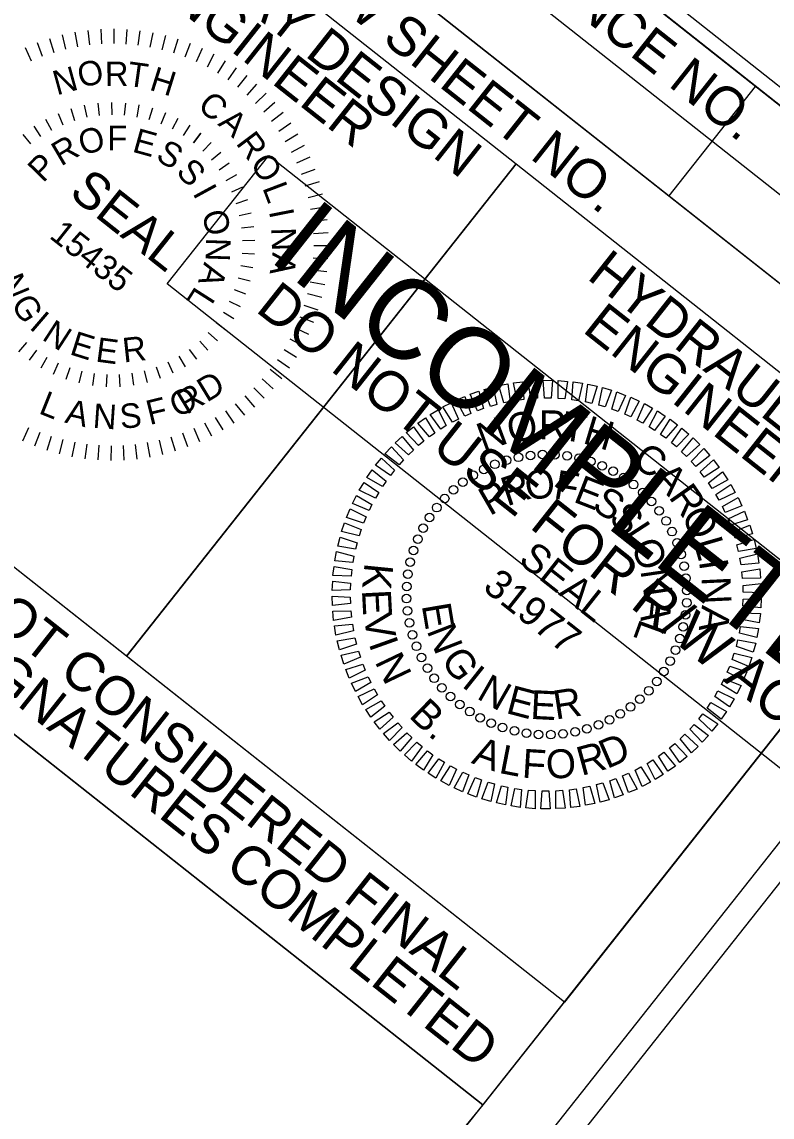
# Model space of a CAD drawing. Extents: x 557005 to 559009, y 505746 to 507841.
# Drawn here: x 558789.4 to 558923.8, y 506648.8 to 506845.2 of the extents above; entities that cross this region are included whole.
import ezdxf

# ---------------------------------------------------------------- set-up
doc = ezdxf.new("R2010")
doc.units = 0
for name, color, linetype in [('Old_Level_21', 7, 'Continuous'), ('Scratch_Level_5', 7, 'Continuous'), ('Sheet Border Standard 30in CELL', 7, 'Continuous'), ('Sheet Plot Border Inside CELL', 7, 'Continuous'), ('Sheet Plot Border Outside CELL', 7, 'Continuous'), ('Sheet Sticker Exception Certification CELL', 7, 'Continuous'), ('Sheet Sticker Incomplete CELL', 7, 'Continuous')]:
    doc.layers.add(name, color=color, linetype=linetype)

msp = doc.modelspace()

# ---------------------------------------------------------------- linework, layer by layer
at = {"layer": 'Old_Level_21'}
for p, q in [((558794.37, 506842.22), (558795.14, 506839.7)), ((558796.62, 506842.83), (558797.24, 506840.27)), ((558798.91, 506843.31), (558799.37, 506840.71)), ((558801.22, 506843.64), (558801.53, 506841.03)), ((558803.55, 506843.84), (558803.7, 506841.21)), ((558805.89, 506843.9), (558805.87, 506841.27)), ((558808.22, 506843.82), (558808.05, 506841.19)), ((558810.55, 506843.59), (558810.22, 506840.98)), ((558812.86, 506843.23), (558812.37, 506840.64)), ((558815.14, 506842.72), (558814.49, 506840.17)), ((558789.99, 506840.59), (558791.06, 506838.17)), ((558792.16, 506841.47), (558793.07, 506839)), ((558817.39, 506842.08), (558816.59, 506839.57)), ((558819.59, 506841.31), (558818.64, 506838.85)), ((558821.75, 506840.4), (558820.65, 506838)), ((558823.84, 506839.37), (558822.6, 506837.04)), ((558825.87, 506838.2), (558824.49, 506835.96)), ((558827.82, 506836.92), (558826.31, 506834.77)), ((558829.7, 506835.53), (558828.06, 506833.46)), ((558831.48, 506834.02), (558829.72, 506832.06)), ((558833.17, 506832.41), (558831.3, 506830.56)), ((558803.04, 506830.58), (558803.27, 506828.39)), ((558805.5, 506830.71), (558805.51, 506828.51)), ((558807.96, 506830.61), (558807.76, 506828.42)), ((558834.77, 506830.7), (558832.78, 506828.96)), ((558795.9, 506828.77), (558796.74, 506826.74)), ((558798.22, 506829.61), (558798.86, 506827.5)), ((558800.61, 506830.21), (558801.04, 506828.06)), ((558810.4, 506830.27), (558809.99, 506828.11)), ((558812.8, 506829.7), (558812.18, 506827.59)), ((558815.13, 506828.89), (558814.31, 506826.85)), ((558836.25, 506828.9), (558834.17, 506827.28)), ((558791.56, 506826.46), (558792.78, 506824.63)), ((558793.67, 506827.72), (558794.71, 506825.78)), ((558817.37, 506827.87), (558816.36, 506825.92)), ((558819.5, 506826.63), (558818.31, 506824.79)), ((558837.63, 506827.01), (558835.45, 506825.52)), ((558789.57, 506825), (558790.96, 506823.29)), ((558821.5, 506825.19), (558820.14, 506823.47)), ((558820.14, 506823.47), (558821.5, 506825.19)), ((558838.88, 506825.04), (558836.62, 506823.69)), ((558823.36, 506823.57), (558821.83, 506821.99)), ((558840.01, 506822.99), (558837.68, 506821.78)), ((558825.04, 506821.78), (558823.37, 506820.35)), ((558841.03, 506820.89), (558838.62, 506819.82)), ((558826.55, 506819.83), (558824.75, 506818.57)), ((558841.91, 506818.72), (558839.44, 506817.8)), ((558827.87, 506817.75), (558825.95, 506816.67)), ((558828.97, 506815.55), (558826.96, 506814.65)), ((558842.66, 506816.51), (558840.14, 506815.74)), ((558829.86, 506813.25), (558827.77, 506812.55)), ((558843.27, 506814.26), (558840.71, 506813.64)), ((558830.52, 506810.87), (558828.38, 506810.39)), ((558843.75, 506811.97), (558841.15, 506811.51)), ((558844.09, 506809.66), (558841.47, 506809.35)), ((558830.95, 506808.45), (558828.77, 506808.17)), ((558844.29, 506807.33), (558841.65, 506807.18)), ((558831.14, 506805.99), (558828.95, 506805.93)), ((558844.34, 506804.99), (558841.71, 506805.01)), ((558831.1, 506803.53), (558828.91, 506803.67)), ((558844.26, 506802.66), (558841.63, 506802.83)), ((558830.82, 506801.09), (558828.65, 506801.44)), ((558830.3, 506798.67), (558828.18, 506799.24)), ((558844.04, 506800.33), (558841.42, 506800.66)), ((558829.55, 506796.33), (558827.49, 506797.1)), ((558843.67, 506798.02), (558841.08, 506798.51)), ((558828.59, 506794.06), (558826.61, 506795.02)), ((558843.16, 506795.74), (558840.61, 506796.39)), ((558827.4, 506791.9), (558825.53, 506793.05)), ((558842.53, 506793.49), (558840.01, 506794.29)), ((558826.02, 506789.86), (558824.26, 506791.19)), ((558841.75, 506791.29), (558839.29, 506792.24)), ((558824.44, 506787.97), (558822.82, 506789.46)), ((558840.84, 506789.13), (558838.45, 506790.23)), ((558788.87, 506786.03), (558790.32, 506787.69)), ((558821.28, 506787.93), (558822.75, 506786.3)), ((558839.81, 506787.04), (558837.48, 506788.28)), ((558790.8, 506784.5), (558792.09, 506786.28)), ((558818.72, 506783.32), (558817.6, 506785.21)), ((558820.77, 506784.68), (558819.47, 506786.45)), ((558838.65, 506785.01), (558836.4, 506786.39)), ((558792.87, 506783.16), (558793.97, 506785.06)), ((558795.06, 506782.03), (558795.97, 506784.03)), ((558797.35, 506781.12), (558798.06, 506783.2)), ((558814.27, 506781.22), (558813.53, 506783.29)), ((558816.55, 506782.17), (558815.61, 506784.15)), ((558837.37, 506783.06), (558835.21, 506784.57)), ((558799.71, 506780.43), (558800.23, 506782.57)), ((558802.14, 506779.97), (558802.44, 506782.15)), ((558804.59, 506779.75), (558804.68, 506781.94)), ((558807.05, 506779.76), (558806.93, 506781.96)), ((558809.5, 506780.02), (558809.17, 506782.18)), ((558811.92, 506780.5), (558811.37, 506782.63)), ((558835.97, 506781.18), (558833.9, 506782.82)), ((558832.85, 506777.71), (558831, 506779.58)), ((558834.46, 506779.4), (558832.5, 506781.16)), ((558831.14, 506776.11), (558829.41, 506778.1)), ((558827.45, 506773.25), (558825.96, 506775.43)), ((558829.34, 506774.63), (558827.72, 506776.71)), ((558825.48, 506772), (558824.13, 506774.26)), ((558789.58, 506770.04), (558790.68, 506772.43)), ((558791.73, 506769.13), (558792.68, 506771.59)), ((558819.16, 506768.97), (558818.25, 506771.44)), ((558821.33, 506769.85), (558820.26, 506772.26)), ((558823.44, 506770.87), (558822.22, 506773.2)), ((558793.93, 506768.35), (558794.73, 506770.87)), ((558796.18, 506767.72), (558796.83, 506770.27)), ((558798.46, 506767.21), (558798.96, 506769.8)), ((558800.77, 506766.84), (558801.1, 506769.46)), ((558812.41, 506767.13), (558811.95, 506769.73)), ((558814.7, 506767.61), (558814.08, 506770.17)), ((558816.95, 506768.22), (558816.18, 506770.74)), ((558803.1, 506766.62), (558803.27, 506769.25)), ((558805.43, 506766.54), (558805.45, 506769.17)), ((558807.77, 506766.59), (558807.63, 506769.23)), ((558810.1, 506766.79), (558809.8, 506769.41))]:
    msp.add_line(p, q, dxfattribs=at)
for points in [[(558873.37, 506776.23), (558872.26, 506779.27), (558873.88, 506779.69), (558874.5, 506776.56)], [(558875.75, 506776.85), (558874.85, 506779.96), (558876.5, 506780.27), (558876.9, 506777.1)], [(558878.16, 506777.31), (558877.49, 506780.47), (558879.15, 506780.66), (558879.33, 506777.47)], [(558880.6, 506777.59), (558880.15, 506780.79), (558881.82, 506780.87), (558881.78, 506777.68)], [(558883.06, 506777.71), (558882.83, 506780.93), (558884.51, 506780.89), (558884.24, 506777.71)], [(558885.52, 506777.65), (558885.52, 506780.88), (558887.18, 506780.72), (558886.7, 506777.57)], [(558887.96, 506777.42), (558888.19, 506780.64), (558889.84, 506780.37), (558889.14, 506777.25)], [(558890.39, 506777.02), (558890.84, 506780.22), (558892.47, 506779.83), (558891.55, 506776.77)], [(558892.78, 506776.45), (558893.45, 506779.61), (558895.05, 506779.11), (558893.92, 506776.12)], [(558868.77, 506774.5), (558867.25, 506777.36), (558868.8, 506778), (558869.85, 506774.98)], [(558871.04, 506775.45), (558869.72, 506778.4), (558871.31, 506778.94), (558872.15, 506775.85)], [(558895.13, 506775.71), (558896.02, 506778.82), (558897.58, 506778.21), (558896.24, 506775.31)], [(558897.42, 506774.82), (558898.52, 506777.86), (558900.03, 506777.14), (558898.5, 506774.34)], [(558864.46, 506772.15), (558862.55, 506774.76), (558864, 506775.62), (558865.46, 506772.78)], [(558866.57, 506773.4), (558864.86, 506776.14), (558866.35, 506776.89), (558867.62, 506773.96)], [(558899.64, 506773.77), (558900.95, 506776.72), (558902.41, 506775.9), (558900.68, 506773.21)], [(558901.78, 506772.56), (558903.3, 506775.42), (558904.7, 506774.5), (558902.78, 506771.93)], [(558862.43, 506770.75), (558860.35, 506773.23), (558861.73, 506774.18), (558863.39, 506771.45)], [(558903.83, 506771.21), (558905.55, 506773.95), (558906.88, 506772.94), (558904.79, 506770.51)], [(558860.51, 506769.22), (558858.27, 506771.54), (558859.57, 506772.59), (558861.42, 506769.98)], [(558905.79, 506769.72), (558907.69, 506772.33), (558908.94, 506771.23), (558906.69, 506768.96)], [(558858.71, 506767.55), (558856.3, 506769.71), (558857.53, 506770.85), (558859.56, 506768.37)], [(558907.63, 506768.09), (558909.71, 506770.57), (558910.89, 506769.38), (558908.48, 506767.27)], [(558857.02, 506765.76), (558854.47, 506767.75), (558855.62, 506768.97), (558857.81, 506766.64)], [(558909.36, 506766.34), (558911.6, 506768.67), (558912.69, 506767.4), (558910.15, 506765.46)], [(558855.46, 506763.86), (558852.78, 506765.67), (558853.84, 506766.96), (558856.19, 506764.8)], [(558910.96, 506764.48), (558913.36, 506766.64), (558914.36, 506765.3), (558911.69, 506763.55)], [(558854.04, 506761.86), (558851.23, 506763.47), (558852.2, 506764.84), (558854.7, 506762.84)], [(558912.43, 506762.51), (558914.97, 506764.5), (558915.88, 506763.09), (558913.09, 506761.52)], [(558852.76, 506759.76), (558849.85, 506761.18), (558850.72, 506762.61), (558853.35, 506760.78)], [(558913.75, 506760.43), (558916.43, 506762.24), (558917.24, 506760.77), (558914.34, 506759.41)], [(558851.63, 506757.58), (558848.63, 506758.79), (558849.4, 506760.27), (558852.14, 506758.64)], [(558914.93, 506758.28), (558917.73, 506759.9), (558918.43, 506758.37), (558915.45, 506757.21)], [(558850.65, 506755.32), (558847.58, 506756.32), (558848.24, 506757.85), (558851.09, 506756.42)], [(558915.95, 506756.04), (558918.86, 506757.46), (558919.45, 506755.89), (558916.4, 506754.95)], [(558849.84, 506753), (558846.7, 506753.78), (558847.25, 506755.36), (558850.2, 506754.13)], [(558916.82, 506753.74), (558919.82, 506754.96), (558920.3, 506753.35), (558917.19, 506752.62)], [(558849.18, 506750.63), (558846, 506751.19), (558846.44, 506752.81), (558849.47, 506751.78)], [(558917.52, 506751.39), (558920.6, 506752.39), (558920.97, 506750.75), (558917.81, 506750.24)], [(558848.7, 506748.22), (558845.48, 506748.56), (558845.81, 506750.2), (558848.91, 506749.39)], [(558918.06, 506748.99), (558921.2, 506749.77), (558921.45, 506748.12), (558918.27, 506747.82)], [(558848.39, 506745.78), (558845.15, 506745.89), (558845.37, 506747.55), (558848.51, 506746.96)], [(558918.43, 506746.56), (558921.62, 506747.12), (558921.75, 506745.45), (558918.56, 506745.38)], [(558848.24, 506743.33), (558845.01, 506743.21), (558845.11, 506744.89), (558848.28, 506744.51)], [(558918.63, 506744.11), (558921.85, 506744.45), (558921.86, 506742.77), (558918.67, 506742.93)], [(558848.27, 506740.87), (558845.05, 506740.53), (558845.03, 506742.21), (558848.23, 506742.05)], [(558918.66, 506741.65), (558921.89, 506741.76), (558921.79, 506740.09), (558918.62, 506740.47)], [(558848.47, 506738.42), (558845.28, 506737.86), (558845.15, 506739.53), (558848.34, 506739.6)], [(558918.51, 506739.2), (558921.74, 506739.08), (558921.53, 506737.42), (558918.39, 506738.02)], [(558848.84, 506735.99), (558845.7, 506735.21), (558845.45, 506736.86), (558848.63, 506737.16)], [(558918.2, 506736.76), (558921.41, 506736.42), (558921.08, 506734.78), (558917.99, 506735.59)], [(558849.37, 506733.59), (558846.3, 506732.59), (558845.93, 506734.22), (558849.09, 506734.74)], [(558917.71, 506734.35), (558920.9, 506733.79), (558920.45, 506732.17), (558917.43, 506733.2)], [(558850.08, 506731.24), (558847.08, 506730.02), (558846.6, 506731.63), (558849.71, 506732.36)], [(558917.06, 506731.98), (558920.2, 506731.2), (558919.65, 506729.62), (558916.7, 506730.85)], [(558850.94, 506728.94), (558848.04, 506727.52), (558847.45, 506729.08), (558850.5, 506730.03)], [(558916.25, 506729.66), (558919.32, 506728.66), (558918.66, 506727.12), (558915.8, 506728.56)], [(558851.97, 506726.7), (558849.17, 506725.08), (558848.47, 506726.6), (558851.45, 506727.76)], [(558915.27, 506727.4), (558918.27, 506726.19), (558917.5, 506724.7), (558914.75, 506726.34)], [(558853.15, 506724.54), (558850.47, 506722.73), (558849.66, 506724.2), (558852.55, 506725.57)], [(558914.14, 506725.22), (558917.05, 506723.8), (558916.18, 506722.37), (558913.55, 506724.19)], [(558854.47, 506722.47), (558851.92, 506720.48), (558851.02, 506721.89), (558853.81, 506723.45)], [(558912.86, 506723.12), (558915.66, 506721.5), (558914.69, 506720.14), (558912.2, 506722.14)], [(558855.94, 506720.5), (558853.54, 506718.34), (558852.54, 506719.68), (558855.21, 506721.43)], [(558911.44, 506721.12), (558914.12, 506719.31), (558913.06, 506718.01), (558910.71, 506720.18)], [(558857.54, 506718.64), (558855.29, 506716.31), (558854.2, 506717.58), (558856.75, 506719.51)], [(558909.88, 506719.21), (558912.43, 506717.23), (558911.28, 506716.01), (558909.09, 506718.33)], [(558859.27, 506716.89), (558857.19, 506714.41), (558856.01, 506715.6), (558858.41, 506717.71)], [(558908.19, 506717.43), (558910.6, 506715.27), (558909.37, 506714.13), (558907.34, 506716.6)], [(558861.11, 506715.26), (558859.21, 506712.64), (558857.96, 506713.75), (558860.2, 506716.02)], [(558863.07, 506713.77), (558861.35, 506711.03), (558860.02, 506712.04), (558862.11, 506714.46)], [(558906.38, 506715.76), (558908.63, 506713.44), (558907.32, 506712.39), (558905.48, 506715)], [(558865.12, 506712.42), (558863.6, 506709.56), (558862.2, 506710.48), (558864.11, 506713.04)], [(558902.44, 506712.83), (558904.34, 506710.22), (558902.9, 506709.36), (558901.44, 506712.2)], [(558904.46, 506714.23), (558906.54, 506711.75), (558905.17, 506710.8), (558903.51, 506713.53)], [(558867.26, 506711.21), (558865.95, 506708.26), (558864.49, 506709.08), (558866.22, 506711.77)], [(558869.48, 506710.16), (558868.38, 506707.12), (558866.86, 506707.84), (558868.4, 506710.64)], [(558900.33, 506711.58), (558902.04, 506708.84), (558900.54, 506708.09), (558899.28, 506711.02)], [(558871.77, 506709.26), (558870.88, 506706.15), (558869.32, 506706.76), (558870.66, 506709.67)], [(558874.12, 506708.53), (558873.45, 506705.37), (558871.85, 506705.87), (558872.98, 506708.86)], [(558893.53, 506708.74), (558894.64, 506705.71), (558893.02, 506705.28), (558892.39, 506708.42)], [(558895.86, 506709.53), (558897.18, 506706.58), (558895.59, 506706.04), (558894.75, 506709.12)], [(558898.13, 506710.48), (558899.65, 506707.62), (558898.1, 506706.98), (558897.05, 506709.99)], [(558876.51, 506707.96), (558876.06, 506704.76), (558874.43, 506705.15), (558875.35, 506708.21)], [(558878.93, 506707.56), (558878.71, 506704.34), (558877.06, 506704.61), (558877.76, 506707.73)], [(558881.38, 506707.33), (558881.38, 506704.1), (558879.72, 506704.25), (558880.2, 506707.41)], [(558883.84, 506707.27), (558884.07, 506704.05), (558882.39, 506704.09), (558882.66, 506707.27)], [(558886.29, 506707.39), (558886.75, 506704.18), (558885.07, 506704.11), (558885.11, 506707.3)], [(558888.74, 506707.67), (558889.41, 506704.51), (558887.75, 506704.31), (558887.56, 506707.5)], [(558891.15, 506708.12), (558892.05, 506705.02), (558890.4, 506704.71), (558890, 506707.88)]]:
    msp.add_lwpolyline(points, close=True, dxfattribs=at)
for centre in [(558878.37, 506767.1), (558880.53, 506767.44), (558882.72, 506767.6), (558884.91, 506767.57), (558887.09, 506767.35), (558889.24, 506766.94), (558872.17, 506764.94), (558874.17, 506765.84), (558876.24, 506766.56), (558891.35, 506766.34), (558893.4, 506765.56), (558870.26, 506763.87), (558895.37, 506764.61), (558897.25, 506763.48), (558866.74, 506761.26), (558868.44, 506762.64), (558899.03, 506762.2), (558865.17, 506759.73), (558900.69, 506760.77), (558902.22, 506759.19), (558863.74, 506758.07), (558903.6, 506757.5), (558862.46, 506756.29), (558904.83, 506755.68), (558861.33, 506754.41), (558905.9, 506753.77), (558860.38, 506752.44), (558906.8, 506751.77), (558859.6, 506750.39), (558907.52, 506749.7), (558859, 506748.28), (558908.06, 506747.57), (558858.59, 506746.13), (558908.4, 506745.41), (558858.37, 506743.95), (558908.56, 506743.22), (558858.33, 506741.76), (558858.49, 506739.57), (558908.53, 506741.03), (558858.84, 506737.41), (558908.31, 506738.85), (558859.38, 506735.28), (558907.9, 506736.7), (558907.3, 506734.59), (558860.1, 506733.21), (558906.52, 506732.54), (558861, 506731.21), (558905.57, 506730.57), (558862.07, 506729.3), (558863.3, 506727.48), (558904.44, 506728.68), (558864.68, 506725.78), (558903.16, 506726.91), (558866.21, 506724.21), (558900.16, 506723.72), (558901.73, 506725.25), (558867.87, 506722.78), (558898.46, 506722.34), (558869.65, 506721.5), (558871.53, 506720.37), (558894.73, 506720.04), (558896.64, 506721.11), (558873.5, 506719.42), (558875.55, 506718.64), (558877.66, 506718.04), (558879.81, 506717.63), (558888.53, 506717.88), (558890.66, 506718.42), (558892.73, 506719.14), (558881.99, 506717.41), (558884.18, 506717.37), (558886.37, 506717.53)]:
    msp.add_circle(centre, 0.777, dxfattribs=at)
at = {"layer": 'Scratch_Level_5'}
msp.add_lwpolyline([(558502.21, 506199.86), (558069.07, 506542.35), (558000.13, 506451.2), (557930.66, 506511.32), (557889.73, 506539.36), (557425.46, 506933.59), (557393.31, 506960), (557371.36, 506969.71), (557385.34, 506999.14), (557443.19, 507138.35), (557378.87, 507175.51), (557803.85, 507716.87), (558807.23, 506891.56), (558715.12, 506775.08), (558872.03, 506651.01)], close=True, dxfattribs=at)
at = {"layer": 'Sheet Border Standard 30in CELL'}
for p, q in [((558814.98, 506901.37), (558971.9, 506777.29)), ((558807.23, 506891.56), (558964.15, 506767.48)), ((558807.23, 506891.56), (558964.15, 506767.48)), ((558920.82, 506833.61), (558905.32, 506814)), ((558877.95, 506819.7), (558808.21, 506731.49))]:
    msp.add_line(p, q, dxfattribs=at)
for points in [[(558979.69, 506787.13), (557803.06, 507717.49), (557151.81, 506893.85), (558328.44, 505963.5)], [(558822.76, 506911.21), (558979.69, 506787.13), (558964.15, 506767.48), (558807.23, 506891.56)], [(558799.47, 506881.76), (558877.95, 506819.7), (558808.18, 506731.46), (558729.7, 506793.51)], [(558877.95, 506819.7), (558956.4, 506757.68), (558886.62, 506669.43), (558808.18, 506731.46)]]:
    msp.add_lwpolyline(points, close=True, dxfattribs=at)
at = {"layer": 'Sheet Plot Border Inside CELL'}
msp.add_lwpolyline([(558991.07, 506781.38), (557683.84, 507815), (557029.43, 506987.37), (558336.66, 505953.74)], close=True, dxfattribs=at)
at = {"layer": 'Sheet Plot Border Outside CELL'}
msp.add_lwpolyline([(559008.53, 506796.2), (557687.57, 507840.68), (557005.31, 506977.82), (558326.27, 505933.34)], close=True, dxfattribs=at)
at = {"layer": 'Sheet Sticker Exception Certification CELL'}
for p, q in [((558729.7, 506793.51), (558886.61, 506669.44)), ((558872.03, 506651.01), (558715.12, 506775.08)), ((558886.6, 506669.43), (558872.03, 506651))]:
    msp.add_line(p, q, dxfattribs=at)
at = {"layer": 'Sheet Sticker Incomplete CELL'}
msp.add_lwpolyline([(558815.43, 506798.18), (558833.65, 506821.22), (558977.78, 506707.25), (558959.56, 506684.21)], close=True, dxfattribs=at)

# ---------------------------------------------------------------- texts
at = {"layer": 'Old_Level_21'}
for s, height, rotation, p in [('O', 4.39, 13.3041, (558799.96, 506833.31)), ('N', 4.39, 15.2636, (558795.68, 506831.97)), ('R', 4.39, 0.2474, (558804.29, 506833.65)), ('T', 4.39, 352.0864, (558808.13, 506833.74)), ('H', 4.39, 342.6545, (558812.09, 506833.04)), ('C', 4.39, 318.9438, (558820.69, 506829.82)), ('A', 4.39, 318.9438, (558824.39, 506826.77)), ('F', 4.39, 359.8274, (558804.73, 506822.17)), ('R', 4.39, 30.4199, (558796.43, 506819.2)), ('O', 4.39, 15.1237, (558800.24, 506821.21)), ('E', 4.39, 344.5312, (558809.03, 506821.93)), ('R', 4.39, 306.9345, (558827.64, 506823.38)), ('S', 4.39, 329.235, (558813.2, 506820.55)), ('P', 4.39, 45.7162, (558793.21, 506816.2)), ('O', 4.39, 303.8777, (558830.18, 506819.74)), ('S', 4.39, 313.9387, (558816.86, 506818.11)), ('SEAL', 6.591, 321.5868, (558797.64, 506814.11)), ('I', 4.39, 298.6425, (558819.93, 506814.47)), ('L', 4.39, 290.7414, (558832.47, 506815.43)), ('O', 4.39, 283.3462, (558821.64, 506810.93)), ('I', 4.39, 281.1659, (558833.66, 506811.24)), ('15435', 4.391, 321.5868, (558794.16, 506806.55)), ('N', 4.39, 271.8715, (558834.1, 506808.25)), ('N', 4.39, 268.05, (558822.46, 506806.52)), ('A', 4.39, 262.1039, (558834.35, 506803.91)), ('A', 4.39, 252.7537, (558822.12, 506802.21)), ('N', 4.39, 292.512, (558785.28, 506798.91)), ('L', 4.39, 237.4575, (558820.53, 506797.92)), ('G', 4.39, 301.2782, (558787.37, 506794.63)), ('I', 4.39, 319.373, (558790.59, 506790.28)), ('N', 4.39, 327.0027, (558792.84, 506788.31)), ('E', 4.39, 342.3948, (558797.8, 506785.62)), ('E', 4.39, 352.3806, (558802.5, 506784.29)), ('R', 4.39, 6.1517, (558807.68, 506784.09)), (' RD', 4.391, 31.2593, (558817.54, 506773.82)), ('O ', 4.391, 22.5865, (558817.03, 506774.2)), ('L', 4.39, 338.2034, (558792.25, 506775.04)), ('F', 4.39, 13.7939, (558812.32, 506772.87)), ('A', 4.39, 347.206, (558796.97, 506773.35)), ('N', 4.39, 356.0286, (558802.03, 506772.39)), ('S', 4.39, 4.9113, (558807.14, 506772.22)), ('O', 5.18, 9.9979, (558876.83, 506769.6)), ('R', 5.18, 359.2727, (558881.99, 506770.36)), ('T', 5.18, 351.0641, (558885.98, 506770.28)), ('N', 5.18, 20.2083, (558872.13, 506767.99)), ('H', 5.18, 343.2748, (558889.73, 506769.68)), ('C', 5.18, 323.6356, (558898.5, 506765.99)), ('R', 5.18, 18.2459, (558876.33, 506758.28)), ('O', 5.18, 6.1465, (558879.8, 506759.42)), ('F', 5.18, 350.3377, (558884.55, 506759.77)), ('E', 5.18, 338.6598, (558888.03, 506759.19)), ('A', 5.18, 314.1306, (558902.17, 506763.18)), ('P', 5.18, 30.0082, (558873.26, 506756.5)), ('R', 5.18, 305.0831, (558905.19, 506759.98)), ('S', 5.18, 326.8975, (558891.34, 506757.91)), ('S', 5.18, 314.9386, (558894.36, 506755.94)), ('O', 5.18, 296.8744, (558907.47, 506756.69)), ('I', 5.18, 302.9796, (558896.91, 506753.39)), ('O', 5.18, 294.2242, (558898.41, 506751.21)), ('L', 5.18, 286.1493, (558909.69, 506751.98)), ('SEAL', 5.181, 321.6738, (558878.18, 506748.31)), ('I', 5.18, 278.6841, (558910.7, 506748.49)), ('K', 5.18, 264.2876, (558850.84, 506748.27)), ('31977', 5.181, 321.6738, (558871.79, 506743.45)), ('N', 5.18, 278.4154, (558900.22, 506746.8)), ('N', 5.18, 272.7442, (558911.18, 506745.63)), ('E', 5.18, 272.9919, (558850.34, 506743.27)), ('A', 5.18, 263.3653, (558900.77, 506742.3)), ('E', 5.18, 279.5244, (558861.05, 506740.57)), ('A', 5.18, 262.5337, (558911.29, 506740.67)), ('V', 5.18, 280.9718, (558850.55, 506738.67)), ('N', 5.18, 291.2867, (558861.91, 506736.04)), ('L', 5.18, 250.0294, (558900.26, 506738.31)), ('I', 5.18, 289.657, (558851.5, 506733.74)), ('N', 5.18, 295.597, (558852.58, 506730.48)), ('G', 5.18, 306.3367, (558864.33, 506730.67)), ('I', 5.18, 321.3868, (558868.05, 506726.11)), ('N', 5.18, 330.1422, (558870.72, 506723.96)), ('E', 5.18, 345.1923, (558875.97, 506721.29)), ('E', 5.18, 356.9545, (558880.45, 506720.21)), ('R', 5.18, 8.7168, (558885.05, 506720.07)), ('B', 5.18, 315.6938, (558858.59, 506720.61)), ('.', 5.18, 324.0359, (558862.02, 506717.23)), ('A', 5.18, 340.0052, (558869.8, 506712.31)), ('D', 5.18, 23.3743, (558894.25, 506711.18)), ('L', 5.18, 349.0526, (558874.71, 506710.54)), ('F', 5.18, 356.5178, (558878.94, 506709.68)), ('O', 5.18, 4.4405, (558883.51, 506709.37)), ('R', 5.18, 15.1656, (558889.67, 506709.96))]:
    msp.add_text(s, height=height, rotation=rotation, dxfattribs=at).set_placement(p)
at = {"layer": 'Sheet Border Standard 30in CELL'}
for s, p in [('PROJECT REFERENCE NO.', (558821.41, 506899.92)), ('ROADWAY DESIGN', (558799.97, 506870.78)), ('R/W SHEET NO.', (558837.44, 506854.67)), ('ENGINEER', (558810.72, 506852.65)), ('HYDRAULICS', (558890.47, 506799.23)), ('ENGINEER', (558889.66, 506789.73))]:
    msp.add_text(s, height=7, rotation=321.6667, dxfattribs=at).set_placement(p)
at = {"layer": 'Sheet Sticker Exception Certification CELL'}
for s, p in [('DOCUMENT NOT CONSIDERED FINAL', (558733.79, 506777.09)), ('UNLESS ALL SIGNATURES COMPLETED', (558729.21, 506769.49))]:
    msp.add_text(s, height=7, rotation=321.6667, dxfattribs=at).set_placement(p)
at = {"layer": 'Sheet Sticker Incomplete CELL'}
for s, height, p in [('INCOMPLETE PLANS', 14.4, (558833.3, 506802.71)), ('DO NOT USE FOR R/W ACQUISITION', 7.2, (558831.09, 506793.38))]:
    msp.add_text(s, height=height, rotation=321.6667, dxfattribs=at).set_placement(p)

doc.saveas('drawing.dxf')
